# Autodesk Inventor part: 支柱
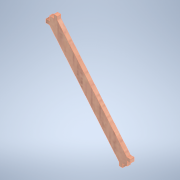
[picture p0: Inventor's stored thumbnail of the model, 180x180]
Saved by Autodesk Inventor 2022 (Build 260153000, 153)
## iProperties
Created: 2024-12
Part Number: 支柱
Material: 木 (オーク)
Document SubType Name: Modeling
Designer: shimizu
Density: 0.76 g/cm^3
Appearance: ホワイト オーク材 - ナチュラル 標準の光沢
Author: shimizu
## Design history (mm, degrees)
sketch "スケッチ1"
  geometry: L1 (-30.797, 30.211)-(-25.116, 30.211); L2 (-25.116, 30.211)-(-25.116, 24.53); L3 (-25.116, 24.53)-(-30.797, 24.53); L4 (-30.797, 24.53)-(-30.797, 30.211); L5 (18.522, -29.109)-(24.203, -29.109); L6 (24.203, -29.109)-(24.203, -34.789); L7 (24.203, -34.789)-(18.522, -34.789); L8 (18.522, -34.789)-(18.522, -29.109); L9 (-30.797, 24.53)-(18.522, -34.789); L10 (-25.116, 30.211)-(24.203, -29.109); L11 (-30.797, 24.53)-(-33.297, 24.53); L12 (-33.297, 24.53)-(-33.297, 27.03); L13 (-33.297, 27.03)-(-30.797, 27.03); L14 (-30.797, 27.03)-(-30.797, 24.53); L15 (-25.116, 30.211)-(-27.616, 30.211); L16 (-27.616, 30.211)-(-27.616, 32.711); L17 (-27.616, 32.711)-(-25.116, 32.711); L18 (-25.116, 32.711)-(-25.116, 30.211); L19 (18.522, -34.789)-(21.022, -34.789); L20 (21.022, -34.789)-(21.022, -37.289); L21 (21.022, -37.289)-(18.522, -37.289); L22 (18.522, -37.289)-(18.522, -34.789); L23 (24.203, -29.109)-(26.703, -29.109); L24 (26.703, -29.109)-(26.703, -31.609); L25 (26.703, -31.609)-(24.203, -31.609); L26 (24.203, -31.609)-(24.203, -29.109); 5 further points
  constraints: 52 end point, 13 parallel, 8 perpendicular, 6 horizontal
  dimensions: "d0" = 8 distance between parallel lines of L9 L10; "d1" = 55 distance between parallel lines of L6 L4; "d2" = 65 distance between parallel lines of L7 L1; "d3" = 2.5 distance of L11.end L12.end; "d4" = 2.5 distance of L3.end L11.end; "d5" = 2.5 distance of L17.end L1.end; "d6" = 2.5 distance of L16.end L17.end; "d7" = 2.5 distance of L21.end L7.end; "d8" = 2.5 distance of L20.end L21.end; "d9" = 2.5 distance of L23.end L24.end; "d10" = 2.5 distance of L5.end L23.end
extrude "押し出し1" new body sketch "スケッチ1" distance "d11" = 2.5; taper "d12" = 0 deg
node "ソリッド1"
